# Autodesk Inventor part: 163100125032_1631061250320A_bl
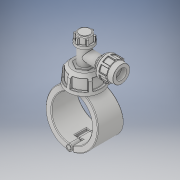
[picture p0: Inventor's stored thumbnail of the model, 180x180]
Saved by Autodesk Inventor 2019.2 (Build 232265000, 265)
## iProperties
Created: 2022-02
Part Number: 163100125032_1631061250320A_bl
Material: Generic
Description: Plassadle Tapper 122x32
Document SubType Name: Modeling
Designer: comp2
Density: 1 g/cm^3
Appearance: Default
Author: comp2
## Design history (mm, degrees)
derived "16310.ipt"
feature "Solid1::16310.ipt" dims "ScaleForDerivedMember" = 10
feature "Solid2::16310.ipt" dims "ScaleForDerivedMember" = 10
feature "Solid3::16310.ipt" dims "ScaleForDerivedMember" = 10
feature "Solid4::16310.ipt" dims "ScaleForDerivedMember" = 10
tag "TaggingFeature1"
body "Solid1"
body "Solid2"
body "Solid3"
body "Solid4"
other parameters: "d" = 122 [user parameter], "d1" = 32 [user parameter], "B" = 157 [user parameter], "E_" = 64 [user parameter], "E1" = 102 [user parameter], "H2" = 144 [user parameter], "H3" = 111 [user parameter], "H_costum" = 52 [user parameter], "d0" = 122 [user parameter], "d2" = 157 [user parameter], "d3" = 61 [user parameter], "d7" = 149.15 [user parameter], "d8" = 85 deg [user parameter], "d9" = 45 deg [user parameter], "d10" = 102 [user parameter], "d11" = 52 [user parameter], "d12" = 36.4 [user parameter], "d13" = 35.7 [user parameter], "d14" = 55.08 [user parameter], "d15" = 2.6 [user parameter], "d16" = 2 [user parameter], "d17" = 2 [user parameter], "d18" = 31.2 [user parameter], "d19" = 7.8 [user parameter], "d20" = 1 [user parameter], "d21" = 30.6 [user parameter], "d22" = 1 [user parameter], "d23" = 15.6 [user parameter], "d24" = 111 [user parameter], "d27" = 144 [user parameter], "d29" = 64 [user parameter], "d31" = 51.2 [user parameter], "d32" = 44.4 [user parameter], "d33" = 15.54 [user parameter], "d34" = 93 deg [user parameter], "d35" = 2 [user parameter], "d36" = 4 [user parameter], "d39" = 45 deg [user parameter], "d40" = 4 [user parameter], "d41" = 5 [user parameter], "d42" = 3.5 [user parameter], "d46" = 51 [user parameter], "d47" = 32 [user parameter], "d48" = 52 [user parameter], "d49" = 3.14 [user parameter], "d51" = 0 [user parameter], "d52" = 24.5 [user parameter], "d53" = 86.35 [user parameter], "d54" = 35 [user parameter], "d55" = 0 [user parameter], "d59" = 0 [user parameter], "d61" = 0 [user parameter], "d62" = 35 [user parameter], "d63" = 0 [user parameter], "d65" = 0 [user parameter], "d67" = 0 [user parameter], "d69" = 0 [user parameter], "d70" = 1 [user parameter], "d71" = 96 [user parameter], "d72" = 0 [user parameter], "d73" = 2 [user parameter], "d77" = 32 [user parameter], "d78" = 86.7 [user parameter], "d79" = 5.1 [user parameter], "d80" = 60 deg [user parameter], "d81" = 5.1 [user parameter], "d84" = 0 [user parameter], "d85" = 1 [user parameter], "d87" = 360 deg [user parameter], "d90" = 0 [user parameter], "d91" = 1 [user parameter], "d93" = 60 deg [user parameter], "d94" = 3.06 [user parameter], "d95" = 3.06 [user parameter], "d97" = 0 [user parameter], "d98" = 0.5 [user parameter], "d100" = 360 deg [user parameter], "d102" = 2 [user parameter], "d105" = 0 [user parameter], "d106" = 45 deg [user parameter], "d107" = 3.2 [user parameter], "d108" = 3.2 [user parameter], "d109" = 2.95332 [user parameter], "d110" = -8 [user parameter], "d112" = 0 [user parameter], "d113" = 0.5 [user parameter], "d115" = 360 deg [user parameter], "d117" = 0.5 [user parameter]
